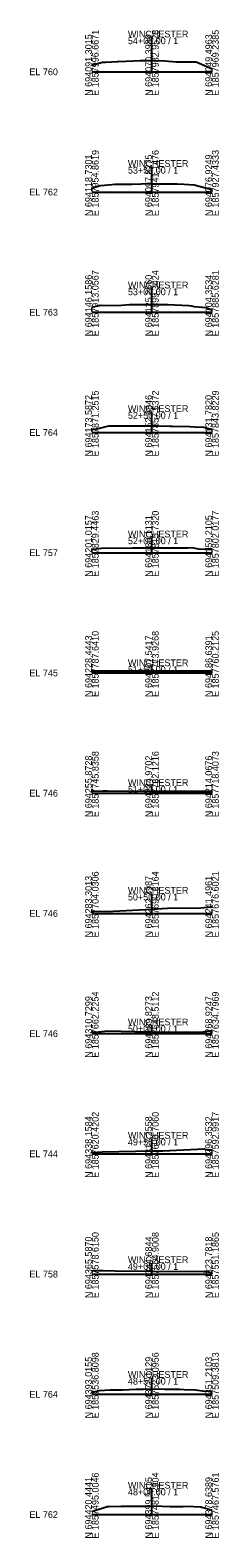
# Model space of a CAD drawing. Extents: x -26 to 53, y 5390 to 6017.
import ezdxf

# ---------------------------------------------------------------- set-up
doc = ezdxf.new("R2010")
doc.units = 0
doc.layers.add('GK_Cells', color=7, linetype='Continuous')
doc.layers.add('XS_X_Ground_Line', color=7, linetype='Continuous')

msp = doc.modelspace()

# ---------------------------------------------------------------- linework, layer by layer
at = {"layer": 'GK_Cells'}
for p, q in [((25, 6000), (25, 6014.3)), ((0, 6000), (25, 6000)), ((25, 6000), (50, 6000)), ((25, 5950), (25, 5960.47)), ((0, 5950), (25, 5950)), ((25, 5950), (50, 5950)), ((25, 5900), (25, 5909.91)), ((0, 5900), (25, 5900)), ((25, 5900), (50, 5900)), ((25, 5850), (25, 5858.5)), ((0, 5850), (25, 5850)), ((25, 5850), (50, 5850)), ((25, 5800), (25, 5806.36)), ((0, 5800), (25, 5800)), ((25, 5800), (50, 5800)), ((0, 5750), (25, 5750)), ((25, 5750), (25, 5752.82)), ((25, 5750), (50, 5750)), ((0, 5700), (25, 5700)), ((25, 5700), (25, 5703)), ((25, 5700), (50, 5700)), ((25, 5650), (25, 5658.19)), ((0, 5650), (25, 5650)), ((25, 5650), (50, 5650)), ((0, 5600), (25, 5600)), ((25, 5600), (25, 5603.46)), ((25, 5600), (50, 5600)), ((25, 5550), (25, 5556.32)), ((0, 5550), (25, 5550)), ((25, 5550), (50, 5550)), ((0, 5500), (25, 5500)), ((25, 5500), (25, 5504.56)), ((25, 5500), (50, 5500)), ((25, 5450), (25, 5456.83)), ((0, 5450), (25, 5450)), ((25, 5450), (50, 5450)), ((25, 5400), (25, 5410.78)), ((0, 5400), (25, 5400)), ((25, 5400), (50, 5400))]:
    msp.add_line(p, q, dxfattribs=at)
at = {"layer": 'XS_X_Ground_Line'}
for points in [[(0, 6002.8), (4.44, 6003.99), (5.75, 6004.01), (10.49, 6004.26), (10.96, 6004.29), (17.44, 6004.52), (20.16, 6004.68), (23.37, 6004.77), (25, 6004.75), (25.96, 6004.74), (30.31, 6004.56), (35.06, 6004.19), (36.26, 6004.14), (37.17, 6004.09), (43.45, 6004.09), (50, 6001.25)], [(0, 5951.68), (2.57, 5952.49), (3.77, 5952.72), (8.36, 5953.15), (9.61, 5953.24), (13.5, 5953.26), (16.59, 5953.3), (20.45, 5953.43), (22.48, 5953.49), (25, 5953.45), (29.46, 5953.37), (34.2, 5953.46), (35.44, 5953.37), (38.2, 5953.32), (42.52, 5952.97), (47.83, 5951.59), (48.44, 5951.53), (49.19, 5951.21), (50, 5950.77)], [(0, 5902.12), (2.46, 5902.69), (3.89, 5902.91), (8.44, 5902.85), (12.35, 5903.02), (15.67, 5903.18), (19.18, 5903.3), (21.59, 5903.29), (25, 5903.28), (25.35, 5903.28), (28.78, 5903.24), (31.72, 5903.18), (34.57, 5903.08), (40.28, 5902.76), (41.66, 5902.61), (42.58, 5902.44), (47.5, 5901.95), (50, 5900.85)], [(0, 5851.37), (1.51, 5851.41), (7.02, 5852.71), (14.49, 5852.77), (15.22, 5852.72), (20.28, 5852.81), (21.23, 5852.83), (25, 5852.77), (26.94, 5852.76), (27.49, 5852.74), (32.59, 5852.7), (33.57, 5852.69), (40.74, 5852.54), (42.67, 5852.39), (46.59, 5852.26), (48.12, 5851.87), (49.18, 5851.46), (50, 5851.05)], [(0, 5801.44), (0.8, 5801.54), (2.69, 5801.77), (3.96, 5801.86), (16.89, 5802.05), (25, 5802.04), (39.89, 5802), (41.54, 5802.12), (45.03, 5801.51), (49.22, 5801.82), (50, 5801.51)], [(0, 5750.84), (3.2, 5750.93), (25, 5750.94), (33.39, 5750.94), (40.79, 5750.93), (46.77, 5750.87), (50, 5750.94)], [(0, 5700.85), (4.6, 5701), (6.41, 5701), (25, 5700.9), (46.98, 5700.79), (49.08, 5700.82), (50, 5700.83)], [(0, 5650.71), (0.73, 5650.73), (3.54, 5650.9), (6.16, 5650.81), (25, 5651.81), (31.53, 5652.15), (45.36, 5652.31), (49.5, 5652.73), (50, 5652.68)], [(0, 5600.67), (1.98, 5600.62), (2.79, 5600.71), (6.57, 5601.15), (23.39, 5600.78), (25, 5600.77), (44.02, 5600.6), (45.49, 5600.65), (48.68, 5601.12), (49.18, 5601.12), (50, 5601.11)], [(0, 5550.63), (2.19, 5550.69), (4.36, 5550.84), (25, 5551.19), (29.47, 5551.27), (46.71, 5552.11), (47.1, 5551.88), (48.15, 5551.67), (50, 5551.67)], [(0, 5501.22), (0.69, 5501.45), (4.75, 5501.52), (9.72, 5501.32), (25, 5501.25), (46.42, 5501.14), (47.45, 5501.1), (50, 5500.66)], [(0, 5450.8), (3.02, 5451.63), (7.45, 5451.9), (10.18, 5451.87), (12.8, 5451.83), (18.42, 5452.1), (20.21, 5452.18), (21.53, 5452.2), (25, 5452.27), (25.43, 5452.28), (30.33, 5452.17), (33.01, 5452.12), (36.48, 5452.09), (38.37, 5451.96), (43.06, 5451.84), (46.06, 5451.4), (48.86, 5451.26), (50, 5450.9)], [(0, 5401.3), (6.42, 5403.33), (7.03, 5403.39), (12.17, 5403.49), (17.48, 5403.42), (23.68, 5403.55), (25.05, 5403.59), (29.28, 5403.45), (32.62, 5403.37), (33.09, 5403.37), (37.88, 5403.41), (39.33, 5403.43), (45.37, 5403.15), (50, 5401.75)]]:
    msp.add_lwpolyline(points, dxfattribs=at)

# ---------------------------------------------------------------- texts
at = {"layer": 'GK_Cells'}
for s, p in [('N 694091.3015', (0, 5990)), ('E 1857996.6671', (2.8, 5990)), ('N 694070.3989', (25, 5990)), ('E 1857982.9528', (27.8, 5990)), ('N 694049.4963', (50, 5990)), ('E 1857969.2385', (52.8, 5990)), ('N 694118.7301', (0, 5940)), ('E 1857954.8619', (2.8, 5940)), ('N 694097.8275', (25, 5940)), ('E 1857941.1476', (27.8, 5940)), ('N 694076.9249', (50, 5940)), ('E 1857927.4333', (52.8, 5940)), ('N 694146.1586', (0, 5890)), ('E 1857913.0567', (2.8, 5890)), ('N 694125.2560', (25, 5890)), ('E 1857899.3424', (27.8, 5890)), ('N 694104.3534', (50, 5890)), ('E 1857885.6281', (52.8, 5890)), ('N 694173.5872', (0, 5840)), ('E 1857871.2515', (2.8, 5840)), ('N 694152.6846', (25, 5840)), ('E 1857857.5372', (27.8, 5840)), ('N 694131.7820', (50, 5840)), ('E 1857843.8229', (52.8, 5840)), ('N 694201.0157', (0, 5790)), ('E 1857829.4463', (2.8, 5790)), ('N 694180.1131', (25, 5790)), ('E 1857815.7320', (27.8, 5790)), ('N 694159.2105', (50, 5790)), ('E 1857802.0177', (52.8, 5790)), ('N 694228.4443', (0, 5740)), ('E 1857787.6410', (2.8, 5740)), ('N 694207.5417', (25, 5740)), ('E 1857773.9268', (27.8, 5740)), ('N 694186.6391', (50, 5740)), ('E 1857760.2125', (52.8, 5740)), ('N 694255.8728', (0, 5690)), ('E 1857745.8358', (2.8, 5690)), ('N 694234.9702', (25, 5690)), ('E 1857732.1216', (27.8, 5690)), ('N 694214.0676', (50, 5690)), ('E 1857718.4073', (52.8, 5690)), ('N 694283.3013', (0, 5640)), ('E 1857704.0306', (2.8, 5640)), ('N 694262.3987', (25, 5640)), ('E 1857690.3164', (27.8, 5640)), ('N 694241.4961', (50, 5640)), ('E 1857676.6021', (52.8, 5640)), ('N 694310.7299', (0, 5590)), ('E 1857662.2254', (2.8, 5590)), ('N 694289.8273', (25, 5590)), ('E 1857648.5112', (27.8, 5590)), ('N 694268.9247', (50, 5590)), ('E 1857634.7969', (52.8, 5590)), ('N 694338.1584', (0, 5540)), ('E 1857620.4202', (2.8, 5540)), ('N 694317.2558', (25, 5540)), ('E 1857606.7060', (27.8, 5540)), ('N 694296.3532', (50, 5540)), ('E 1857592.9917', (52.8, 5540)), ('N 694365.5870', (0, 5490)), ('E 1857578.6150', (2.8, 5490)), ('N 694344.6844', (25, 5490)), ('E 1857564.9008', (27.8, 5490)), ('N 694323.7818', (50, 5490)), ('E 1857551.1865', (52.8, 5490)), ('N 694393.0155', (0, 5440)), ('E 1857536.8098', (2.8, 5440)), ('N 694372.1129', (25, 5440)), ('E 1857523.0956', (27.8, 5440)), ('N 694351.2103', (50, 5440)), ('E 1857509.3813', (52.8, 5440)), ('N 694420.4441', (0, 5390)), ('E 1857495.0046', (2.8, 5390)), ('N 694399.5415', (25, 5390)), ('E 1857481.2904', (27.8, 5390)), ('N 694378.6389', (50, 5390)), ('E 1857467.5761', (52.8, 5390))]:
    msp.add_text(s, height=2.8, rotation=90, dxfattribs=at).set_placement(p)
for s, p in [('WINCHESTER', (15, 6014.3)), ('54+00.00 / 1', (15, 6011.5)), ('EL 760', (-26, 5998.6)), ('WINCHESTER', (15, 5960.47)), ('53+50.00 / 1', (15, 5957.67)), ('EL 762', (-26, 5948.6)), ('WINCHESTER', (15, 5909.91)), ('53+00.00 / 1', (15, 5907.11)), ('EL 763', (-26, 5898.6)), ('WINCHESTER', (15, 5858.5)), ('52+50.00 / 1', (15, 5855.7)), ('EL 764', (-26, 5848.6)), ('WINCHESTER', (15, 5806.36)), ('52+00.00 / 1', (15, 5803.56)), ('EL 757', (-26, 5798.6)), ('EL 745', (-26, 5748.6)), ('WINCHESTER', (15, 5752.82)), ('51+50.00 / 1', (15, 5750.02)), ('EL 746', (-26, 5698.6)), ('WINCHESTER', (15, 5703)), ('51+00.00 / 1', (15, 5700.2)), ('WINCHESTER', (15, 5658.19)), ('50+50.00 / 1', (15, 5655.39)), ('EL 746', (-26, 5648.6)), ('WINCHESTER', (15, 5603.46)), ('EL 746', (-26, 5598.6)), ('50+00.00 / 1', (15, 5600.66)), ('WINCHESTER', (15, 5556.32)), ('49+50.00 / 1', (15, 5553.52)), ('EL 744', (-26, 5548.6)), ('WINCHESTER', (15, 5504.56)), ('EL 758', (-26, 5498.6)), ('49+00.00 / 1', (15, 5501.76)), ('WINCHESTER', (15, 5456.83)), ('48+50.00 / 1', (15, 5454.03)), ('EL 764', (-26, 5448.6)), ('WINCHESTER', (15, 5410.78)), ('48+00.00 / 1', (15, 5407.98)), ('EL 762', (-26, 5398.6))]:
    msp.add_text(s, height=2.8, dxfattribs=at).set_placement(p)

doc.saveas('drawing.dxf')
